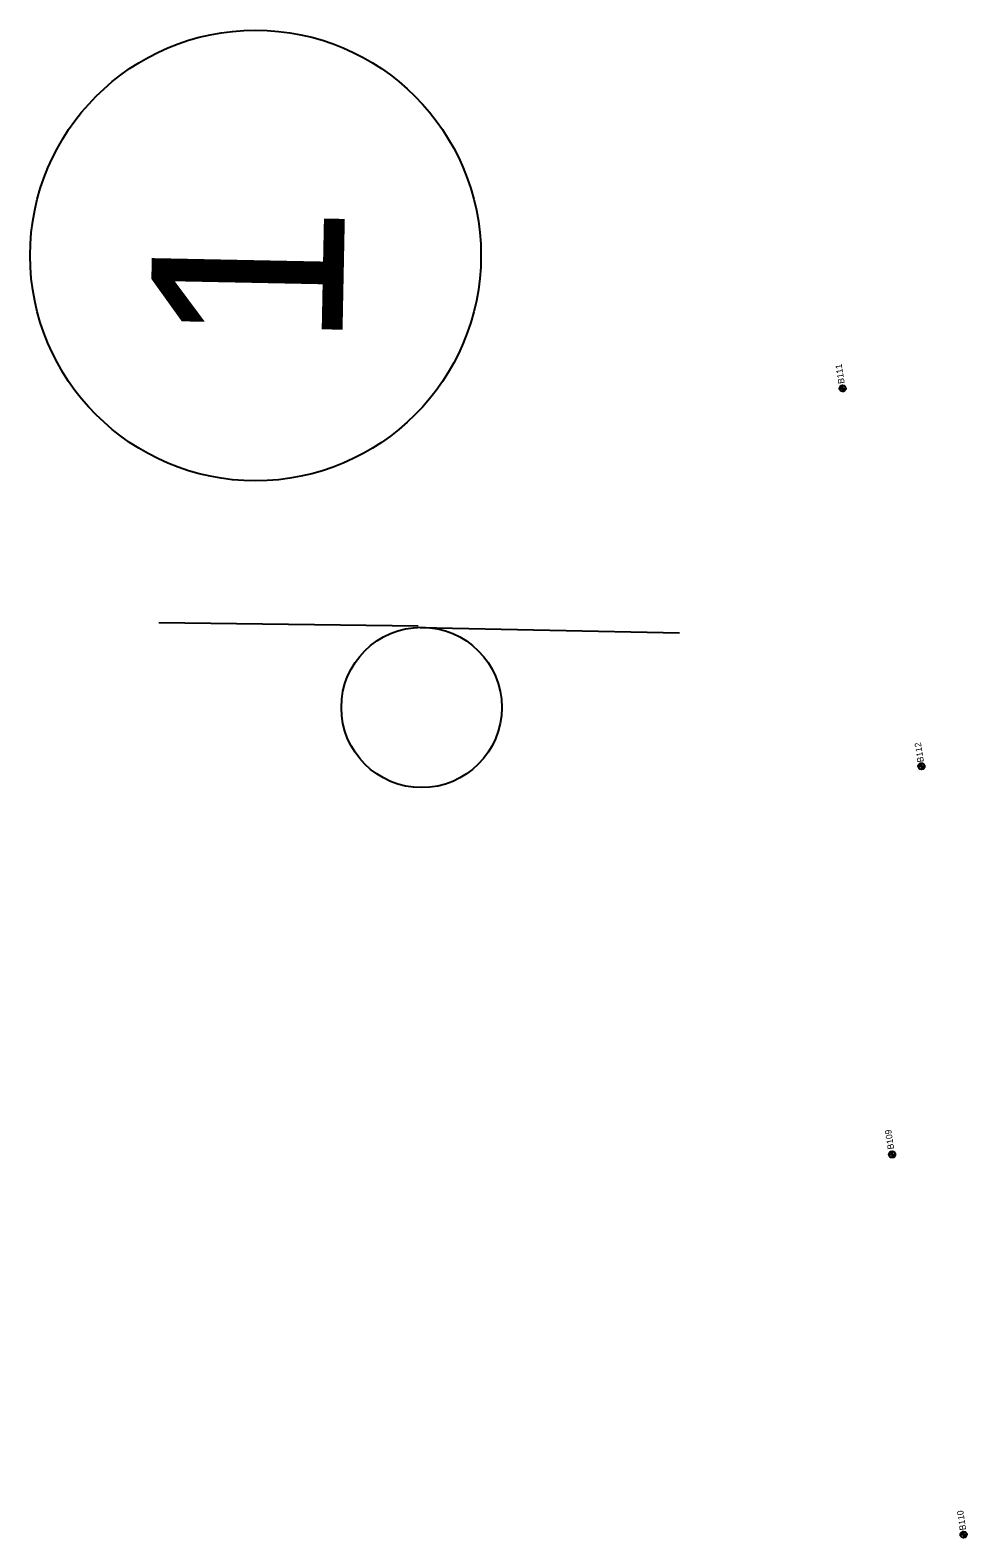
# Model space of a CAD drawing. Extents: x 311409 to 379449, y 121539 to 224848.
# Drawn here: x 354005 to 355467, y 188393 to 190746 of the extents above; entities that cross this region are included whole.
import ezdxf

# ---------------------------------------------------------------- set-up
doc = ezdxf.new("R2010")
doc.units = 0
for name, color, linetype in [('CA-TEXT', 7, 'Continuous'), ('E_SOIL_BORE1 [KAPUR_CADDS_LEVELS]', 7, 'Continuous'), ('E_SOIL_BORE2 [KAPUR_CADDS_LEVELS]', 7, 'Continuous'), ('P_MARK', 7, 'Continuous'), ('SIGNS-POLES', 7, 'Continuous')]:
    doc.layers.add(name, color=color, linetype=linetype)

msp = doc.modelspace()

# ---------------------------------------------------------------- linework, layer by layer
at = {"layer": 'CA-TEXT'}
msp.add_circle((354356.4, 190394.5), 351.8, dxfattribs=at)
at = {"layer": 'P_MARK'}
for p, q in [((355272.7, 190192.1), (355272.7, 190182.1)), ((355267.7, 190187.1), (355277.7, 190187.1)), ((355395.7, 189602.1), (355395.7, 189592.1)), ((355390.7, 189597.1), (355400.7, 189597.1)), ((355344.9, 188991.1), (355354.9, 188991.1)), ((355349.9, 188996.1), (355349.9, 188986.1)), ((355461.5, 188402.5), (355461.5, 188392.5)), ((355456.5, 188397.5), (355466.5, 188397.5))]:
    msp.add_line(p, q, dxfattribs=at)
for centre in [(355272.7, 190187.1), (355395.7, 189597.1), (355349.9, 188991.1), (355461.5, 188397.5)]:
    msp.add_circle(centre, 5, dxfattribs=at)
for centre, radius, start, end in [((355272.7, 190187.1), 4.5, 89.9869, 179.9869), ((355272.7, 190187.1), 4, 89.9869, 179.9869), ((355272.7, 190187.1), 3.5, 89.9869, 179.9869), ((355272.7, 190187.1), 3, 89.9869, 179.9869), ((355272.7, 190187.1), 2.5, 89.9869, 179.9869), ((355272.7, 190187.1), 2, 89.9869, 179.9869), ((355272.7, 190187.1), 1.5, 89.9869, 179.9869), ((355272.7, 190187.1), 1, 89.9869, 179.9869), ((355272.7, 190187.1), 0.5, 89.9869, 179.9869), ((355272.7, 190187.1), 4.5, 269.9869, 359.9869), ((355272.7, 190187.1), 4, 269.9869, 359.9869), ((355272.7, 190187.1), 3.5, 269.9869, 359.9869), ((355272.7, 190187.1), 3, 269.9869, 359.9869), ((355272.7, 190187.1), 2.5, 269.9869, 359.9869), ((355272.7, 190187.1), 2, 269.9869, 359.9869), ((355272.7, 190187.1), 1.5, 269.9869, 359.9869), ((355272.7, 190187.1), 1, 269.9869, 359.9869), ((355272.7, 190187.1), 0.5, 269.9869, 359.9869), ((355395.7, 189597.1), 4.5, 89.9869, 179.9869), ((355395.7, 189597.1), 4, 89.9869, 179.9869), ((355395.7, 189597.1), 3.5, 89.9869, 179.9869), ((355395.7, 189597.1), 3, 89.9869, 179.9869), ((355395.7, 189597.1), 2.5, 89.9869, 179.9869), ((355395.7, 189597.1), 2, 89.9869, 179.9869), ((355395.7, 189597.1), 1.5, 89.9869, 179.9869), ((355395.7, 189597.1), 1, 89.9869, 179.9869), ((355395.7, 189597.1), 0.5, 89.9869, 179.9869), ((355395.7, 189597.1), 4.5, 269.9869, 359.9869), ((355395.7, 189597.1), 4, 269.9869, 359.9869), ((355395.7, 189597.1), 3.5, 269.9869, 359.9869), ((355395.7, 189597.1), 3, 269.9869, 359.9869), ((355395.7, 189597.1), 2.5, 269.9869, 359.9869), ((355395.7, 189597.1), 2, 269.9869, 359.9869), ((355395.7, 189597.1), 1.5, 269.9869, 359.9869), ((355395.7, 189597.1), 1, 269.9869, 359.9869), ((355395.7, 189597.1), 0.5, 269.9869, 359.9869), ((355349.9, 188991.1), 4.5, 89.9869, 179.9869), ((355349.9, 188991.1), 4, 89.9869, 179.9869), ((355349.9, 188991.1), 3.5, 89.9869, 179.9869), ((355349.9, 188991.1), 3, 89.9869, 179.9869), ((355349.9, 188991.1), 2.5, 89.9869, 179.9869), ((355349.9, 188991.1), 2, 89.9869, 179.9869), ((355349.9, 188991.1), 1.5, 89.9869, 179.9869), ((355349.9, 188991.1), 1, 89.9869, 179.9869), ((355349.9, 188991.1), 0.5, 89.9869, 179.9869), ((355349.9, 188991.1), 4.5, 269.9869, 359.9869), ((355349.9, 188991.1), 4, 269.9869, 359.9869), ((355349.9, 188991.1), 3.5, 269.9869, 359.9869), ((355349.9, 188991.1), 3, 269.9869, 359.9869), ((355349.9, 188991.1), 2.5, 269.9869, 359.9869), ((355349.9, 188991.1), 2, 269.9869, 359.9869), ((355349.9, 188991.1), 1.5, 269.9869, 359.9869), ((355349.9, 188991.1), 1, 269.9869, 359.9869), ((355349.9, 188991.1), 0.5, 269.9869, 359.9869), ((355461.5, 188397.5), 4.5, 89.9869, 179.9869), ((355461.5, 188397.5), 4, 89.9869, 179.9869), ((355461.5, 188397.5), 3.5, 89.9869, 179.9869), ((355461.5, 188397.5), 3, 89.9869, 179.9869), ((355461.5, 188397.5), 2.5, 89.9869, 179.9869), ((355461.5, 188397.5), 2, 89.9869, 179.9869), ((355461.5, 188397.5), 1.5, 89.9869, 179.9869), ((355461.5, 188397.5), 1, 89.9869, 179.9869), ((355461.5, 188397.5), 0.5, 89.9869, 179.9869), ((355461.5, 188397.5), 4.5, 269.9869, 359.9869), ((355461.5, 188397.5), 4, 269.9869, 359.9869), ((355461.5, 188397.5), 3.5, 269.9869, 359.9869), ((355461.5, 188397.5), 3, 269.9869, 359.9869), ((355461.5, 188397.5), 2.5, 269.9869, 359.9869), ((355461.5, 188397.5), 2, 269.9869, 359.9869), ((355461.5, 188397.5), 1.5, 269.9869, 359.9869), ((355461.5, 188397.5), 1, 269.9869, 359.9869), ((355461.5, 188397.5), 0.5, 269.9869, 359.9869)]:
    msp.add_arc(centre, radius, start, end, dxfattribs=at)
at = {"layer": 'SIGNS-POLES'}
for p, q in [((354205.4, 189821.7), (354610.4, 189816.5)), ((354613.3, 189813.5), (355018.2, 189805.3))]:
    msp.add_line(p, q, dxfattribs=at)
msp.add_circle((354615.5, 189688.9), 125.2, dxfattribs=at)

# ---------------------------------------------------------------- texts
at = {"layer": 'CA-TEXT'}
msp.add_text('1', height=300, rotation=88.8468, dxfattribs=at).set_placement((354491.6, 190248.1))
at = {"layer": 'E_SOIL_BORE1 [KAPUR_CADDS_LEVELS]'}
for s, p in [('B111', (355275.9, 190195)), ('B112', (355399.6, 189604.1))]:
    msp.add_text(s, height=10, rotation=98.957, dxfattribs=at).set_placement(p)
at = {"layer": 'E_SOIL_BORE2 [KAPUR_CADDS_LEVELS]'}
for s, p in [('B109', (355353.2, 188999.7)), ('B110', (355465.6, 188405.1))]:
    msp.add_text(s, height=10, rotation=98.957, dxfattribs=at).set_placement(p)

doc.saveas('drawing.dxf')
